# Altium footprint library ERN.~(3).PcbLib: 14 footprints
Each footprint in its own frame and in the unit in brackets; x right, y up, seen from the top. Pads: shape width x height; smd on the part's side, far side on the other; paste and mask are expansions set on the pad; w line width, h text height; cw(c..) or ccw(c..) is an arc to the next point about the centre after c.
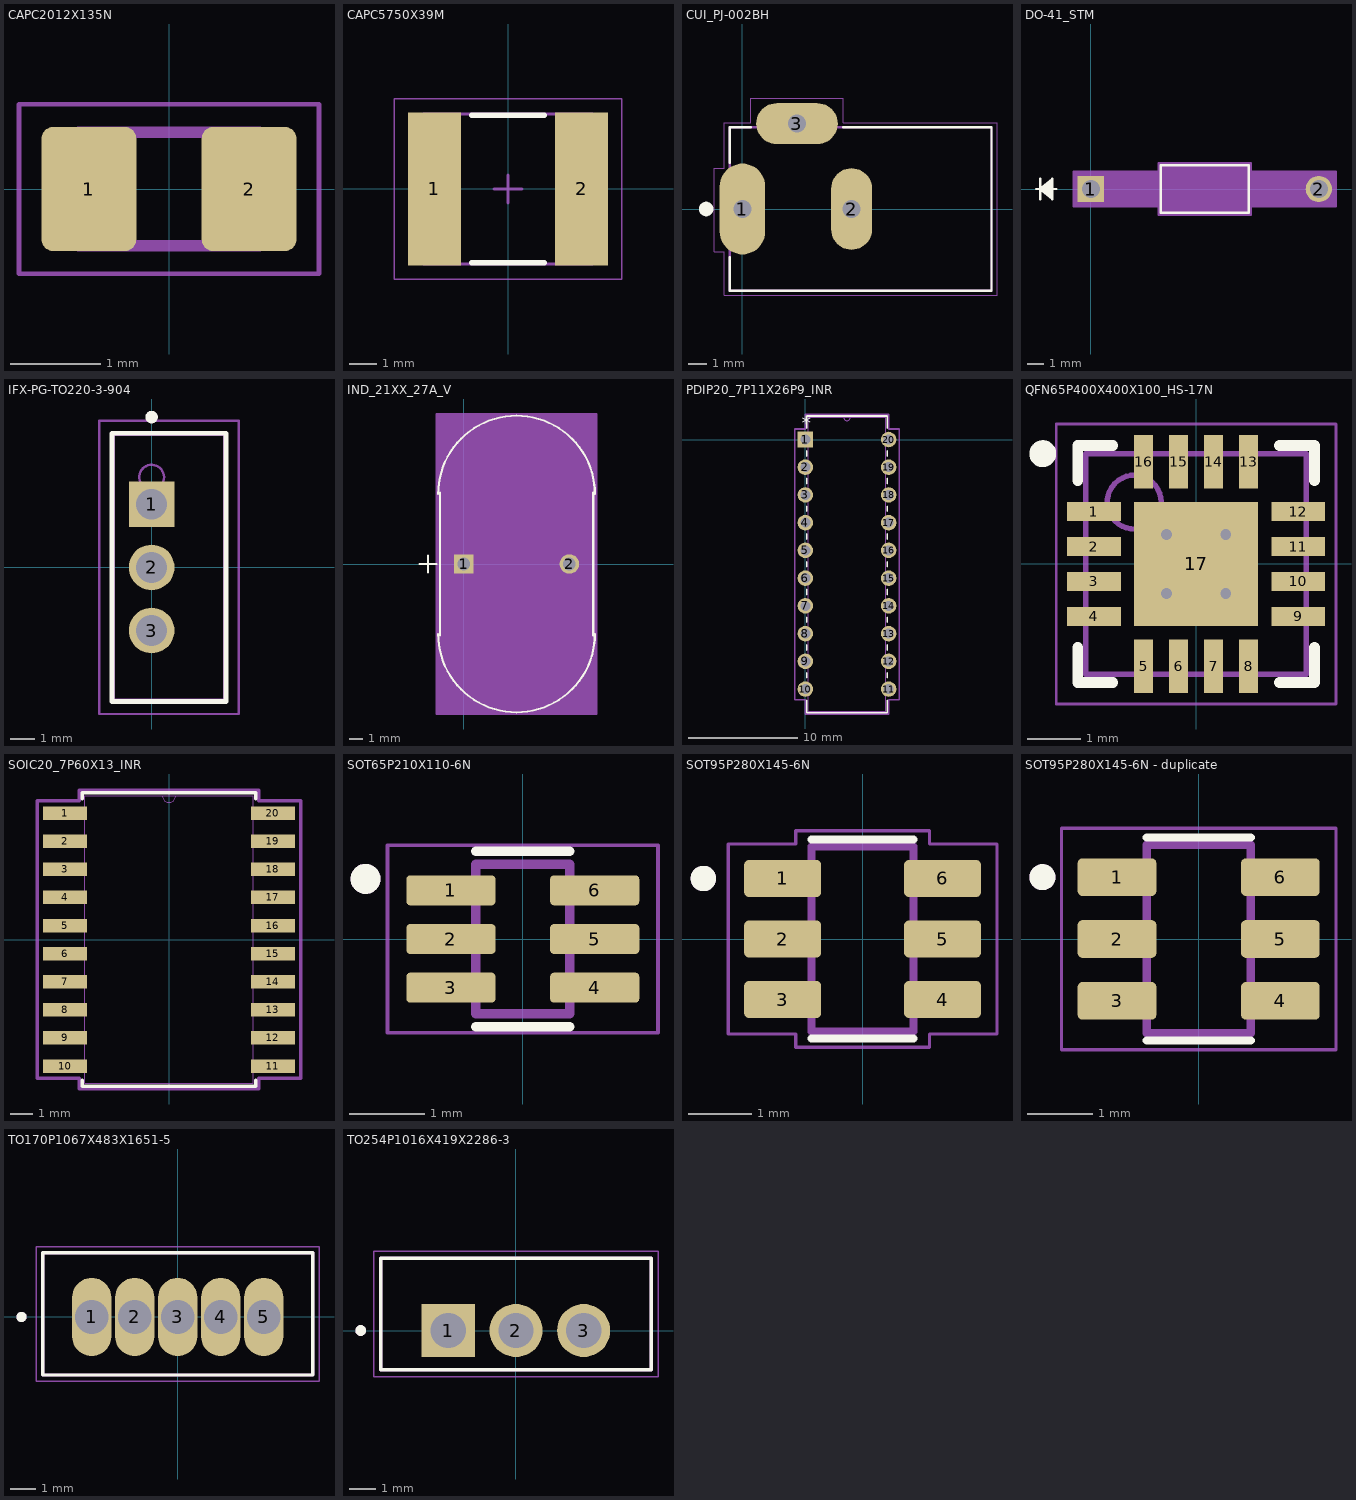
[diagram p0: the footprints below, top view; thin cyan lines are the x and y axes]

## CAPC2012X135N [mm]
pads (2):
  rrect25% 1.05x1.38 smd paste+0 mask+0.102: 1(-0.888,0) 2(0.888,0)
Mechanical 13:
  lines w0.127: -1,-0.63 1,-0.63 1,0.63 -1,0.63 -1,-0.63
Mechanical 15:
  lines w0.05: -1.663,-0.94 1.663,-0.94 1.663,0.94 -1.663,0.94 -1.663,-0.94
3D body "step_temp.STEP": height 1.35, standoff 0, extent -1,-0.625 1,0.625

## CAPC5750X39M [mm] "Chip Capacitor, 2-Leads, Body 5.70x5.00mm, IPC Low Density"
height 3.9
pads (2):
  rect 1.9x5.5 smd: 1(-2.65,0) 2(2.65,0)
Top Overlay:
  lines w0.2: -1.3,-2.65 1.3,-2.65 ; -1.3,2.65 1.3,2.65
Mechanical 13:
  lines w0.1: -3.05,-2.7 -3.05,2.7 3.05,2.7 3.05,-2.7 -3.05,-2.7
Mechanical 15:
  lines w0.05: -4.1,-3.25 -4.1,3.25 4.1,3.25 4.1,-3.25 -4.1,-3.25
  lines w0.1: -0.5,0 0.5,0 ; 0,-0.5 0,0.5
3D body "CAPC5750X39M.step": height 3.9, standoff 0, extent -3.05,-2.7 3.05,2.7

## CUI_PJ-002BH [mm]
pads (3):
  oval 2.5x5 hole 1 square: 1(0,0)
  oval 2.25x4.5 hole 1 square: 2(6,0)
  oval 4.5x2.25 hole 1 square: 3(3,4.7)
Top Overlay:
  circle w0.4: c-2,0 r0.2
  lines w0.127: -0.7,-2.65 -0.7,-4.5 13.7,-4.5 13.7,4.5 5.55,4.5 ; -0.7,2.55 -0.7,4.5 0.45,4.5
Mechanical 13:
  lines w0.127: -0.7,-4.5 13.7,-4.5 13.7,4.5 -0.7,4.5 -0.7,-4.5
Mechanical 15:
  lines w0.05: -1.55,-2.35 -1.55,2.25 -1,2.25 -1,4.75 0.45,4.75 0.45,6.1 5.55,6.1 5.55,4.75 14,4.75 14,-4.75 -1,-4.75 -1,-2.35 -1.55,-2.35
3D body "step_temp.STEP": height 4.5, standoff -10, extent -0.723,-4.701 13.677,4.699

## DO-41_STM [mil]
pads (2):
  rect 64x64 hole 44 paste-99999 mask+0: 1(0,0)
  round 64 hole 44 paste-99999 mask+0: 2(557,0)
Top Overlay:
  lines w6: -134,0 -84,0 ; -124,-25 -124,25 ; -94,-20 -124,0 ; -94,-15 -124,0 ; -94,-10 -124,0 ; -94,-5 -124,0 ; -94,5 -124,0 ; -94,10 -124,0 ; -94,15 -124,0 ; -94,20 -124,0 ; -124,0 -94,-25 -94,25 -124,0 ; 171,-58 171,58 386,58 386,-58 171,-58
  text ".Designator" at 141,-25 h50
Mechanical 13:
  lines w1: -134,0 -84,0 ; -124,-25 -124,25 ; -94,-20 -124,0 ; -94,-15 -124,0 ; -94,-10 -124,0 ; -94,-5 -124,0 ; -94,5 -124,0 ; -94,10 -124,0 ; -94,15 -124,0 ; -94,20 -124,0 ; 0,0 176,0 ; 381,0 557,0 ; -124,0 -94,-25 -94,25 -124,0 ; 176,-53 176,53 381,53 381,-53 176,-53
  text ".Designator" at 141,-25 h50
Mechanical 15:
  region: 381,-53 176,-53 176,53 381,53
  region: 166,-42 -42,-42 -42,42 166,42 166,63 391,63 391,42 599,42 599,-42 391,-42 391,-63 166,-63
  lines w6: -42,-42 166,-42 166,-63 391,-63 391,-42 599,-42 599,42 391,42 391,63 166,63 166,42 -42,42 -42,-42
3D body "DO-41_STM.step": height 106.06, standoff -100, extent -17.01,-52.71 574.02,52.71

## IFX-PG-TO220-3-904 [mm] "TO,flange mount,2.54mm pitch;3 pin,4.45mm L X 10.66mm W X 19.15mm H body"
height 19.15
pads (3):
  rect 1.84x1.84 hole 1.24 paste-2539.97 mask+0: 1(0,2.54)
  round 1.84 hole 1.24 paste-2539.97 mask+0: 2(0,0) 3(0,-2.54)
Top Overlay:
  circle w0.25: c0,6.05 r0.125
  lines w0.2: -1.6,-5.4 -1.6,5.4 3,5.4 3,-5.4 -1.6,-5.4
Mechanical 3:
  text ".DESIGNATOR" at 0,0 h1.2
Mechanical 13:
  circle w0.1: c0,3.632 r0.5
  lines w0.1: -1.52,-5.33 -1.52,5.33 2.93,5.33 2.93,-5.33 -1.52,-5.33
Mechanical 15:
  lines w0.1: -0.5,0 0.5,0 ; 0,-0.5 0,0.5 ; -2.1,-5.9 -2.1,5.9 3.5,5.9 3.5,-5.9 -2.1,-5.9
3D body "PG-TO220-3-904_Z8B00185321_V03_3D.stp": height 19.1, standoff -9.85, extent -1.53,-5.33 2.93,5.33

## IND_21XX_27A_V [mil]
pads (2):
  rect 57x57 hole 37 paste-99999 mask+0: 1(0,0)
  round 57 hole 37 paste-99999 mask+0: 2(310,0)
Top Overlay:
  lines w6: -130,0 -80,0 ; -105,-25 -105,25 ; -75,-205 ccw(c155,-205) 385,-205 ; -75,205 cw(c155,205) 385,205 ; -70,-210 -70,210 ; 380,-210 380,210
  text ".Designator" at 17.5,-25 h50
Mechanical 13:
  lines w1: -130,0 -80,0 ; -105,-25 -105,25 ; -70,-205 ccw(c155,-205) 380,-205 380,205 ccw(c155,205) -70,205 -70,-205
  text ".Designator" at 17.5,-25 h50
Mechanical 15:
  region: 390,-440 -80,-440 -80,440 390,440
  lines w6: -80,-440 -80,440 390,440 390,-440 -80,-440

## PDIP20_7P11X26P9_INR [mil]
pads (20):
  rect 56x56 hole 36 paste-99999 mask+0: 1(0,0)
  round 56 hole 36 paste-99999 mask+0: 2(0,-100) 3(0,-200) 4(0,-300) 5(0,-400) 6(0,-500) 7(0,-600) 8(0,-700) 9(0,-800) 10(0,-900) 11(300,-900) 12(300,-800) 13(300,-700) 14(300,-600) 15(300,-500) 16(300,-400) 17(300,-300) 18(300,-200) 19(300,-100) 20(300,0)
Top Overlay:
  lines w6: 5,-940.79 5,-985 295,-985 295,-940.79 ; 5,-859.21 5,-840.79 ; 5,-759.21 5,-740.79 ; 5,-659.21 5,-640.79 ; 5,-559.21 5,-540.79 ; 5,-459.21 5,-440.79 ; 5,-359.21 5,-340.79 ; 5,-259.21 5,-240.79 ; 5,-159.21 5,-140.79 ; 5,-59.21 5,-41.1 ; 5,41.1 5,85 295,85 295,40.79 ; 295,-859.21 295,-840.79 ; 295,-759.21 295,-740.79 ; 295,-659.21 295,-640.79 ; 295,-559.21 295,-540.79 ; 295,-459.21 295,-440.79 ; 295,-359.21 295,-340.79 ; 295,-259.21 295,-240.79 ; 295,-159.21 295,-140.79 ; 295,-59.21 295,-40.79
  text "*" at -12.5,33 h50
  text ".Designator" at 12.5,-475 h50
Mechanical 13:
  lines w1: 138,80 ccw(c150,80) 162,80 ; -18,-918 -18,-882 10,-882 10,-918 -18,-918 ; -18,-818 -18,-782 10,-782 10,-818 -18,-818 ; -18,-718 -18,-682 10,-682 10,-718 -18,-718 ; -18,-618 -18,-582 10,-582 10,-618 -18,-618 ; -18,-518 -18,-482 10,-482 10,-518 -18,-518 ; -18,-418 -18,-382 10,-382 10,-418 -18,-418 ; -18,-318 -18,-282 10,-282 10,-318 -18,-318 ; -18,-218 -18,-182 10,-182 10,-218 -18,-218 ; -18,-118 -18,-82 10,-82 10,-118 -18,-118 ; -18,-18 -18,18 10,18 10,-18 -18,-18 ; 10,-980 290,-980 290,80 10,80 10,-980 ; 290,-918 290,-882 318,-882 318,-918 290,-918 ; 290,-818 290,-782 318,-782 318,-818 290,-818 ; 290,-718 290,-682 318,-682 318,-718 290,-718 ; 290,-618 290,-582 318,-582 318,-618 290,-618 ; 290,-518 290,-482 318,-482 318,-518 290,-518 ; 290,-418 290,-382 318,-382 318,-418 290,-418 ; 290,-318 290,-282 318,-282 318,-318 290,-318 ; 290,-218 290,-182 318,-182 318,-218 290,-218 ; 290,-118 290,-82 318,-82 318,-118 290,-118 ; 290,-18 290,18 318,18 318,-18 290,-18
  text ".Designator" at 12.5,-475 h50
  text "*" at 7.5,-25 h50
Mechanical 15:
  lines w6: -38,-938 -38,38 0,38 0,90 300,90 300,38 338,38 338,-938 300,-938 300,-990 0,-990 0,-938 -38,-938
3D body "PDIP20_7P11X26P9_INR.step": height 217.09, standoff -100, extent -7.01,-980 320.98,80

## QFN65P400X400X100_HS-17N [mm] "QFN, 16-Leads, Body 4.00x4.00mm, Pitch 0.65mm, Thermal Pad 2.30x2.30mm, IPC Medium Density"
height 1
pads (17):
  rect 1x0.35 smd: 1(-1.9,0.975) 2(-1.9,0.325) 3(-1.9,-0.325) 4(-1.9,-0.975) 9(1.9,-0.975) 10(1.9,-0.325) 11(1.9,0.325) 12(1.9,0.975)
  rect 0.35x1 smd: 5(-0.975,-1.9) 6(-0.325,-1.9) 7(0.325,-1.9) 8(0.975,-1.9) 13(0.975,1.9) 14(0.325,1.9) 15(-0.325,1.9) 16(-0.975,1.9)
  rect 2.3x2.3 smd: 17(0,0)
via -0.55,0.55 diameter 0.5 hole 0.2
via 0.55,0.55 diameter 0.5 hole 0.2
via -0.55,-0.55 diameter 0.5 hole 0.2
via 0.55,-0.55 diameter 0.5 hole 0.2
Top Overlay:
  circle w0.25: c-2.85,2.05 r0.125
  lines w0.2: -2.2,-1.55 -2.2,-2.2 -1.55,-2.2 ; -2.2,1.55 -2.2,2.2 -1.55,2.2 ; 1.55,-2.2 2.2,-2.2 2.2,-1.55 ; 1.55,2.2 2.2,2.2 2.2,1.55
Mechanical 13:
  circle w0.1: c-1.15,1.15 r0.5
  lines w0.1: -2.05,-2.05 -2.05,2.05 2.05,2.05 2.05,-2.05 -2.05,-2.05
Mechanical 15:
  lines w0.05: -2.6,-2.6 -2.6,2.6 2.6,2.6 2.6,-2.6 -2.6,-2.6
  lines w0.1: -0.5,0 0.5,0 ; 0,-0.5 0,0.5
3D body "QFN65P400X400X100_HS-17N.step": height 1, standoff 0, extent -2.051,-2.051 2.051,2.051

## SOIC20_7P60X13_INR [mil]
pads (20):
  rect 79x24 smd paste+0 mask+0: 1(-185.04,225) 2(-185.04,175) 3(-185.04,125) 4(-185.04,75) 5(-185.04,25) 6(-185.04,-25) 7(-185.04,-75) 8(-185.04,-125) 9(-185.04,-175) 10(-185.04,-225) 11(185.04,-225) 12(185.04,-175) 13(185.04,-125) 14(185.04,-75) 15(185.04,-25) 16(185.04,25) 17(185.04,75) 18(185.04,125) 19(185.04,175) 20(185.04,225)
Top Overlay:
  lines w6: -154.61,-250.1 -154.61,-260.91 154.61,-260.91 154.61,-250.1 ; -154.61,250.1 -154.61,260.91 154.61,260.91 154.61,250.1
  text ".Designator" at -245,300 h50
Mechanical 13:
  lines w1: -12,255.91 ccw(c0,255.91) 12,255.91 ; -149.61,-255.91 -149.61,255.91 149.61,255.91 149.61,-255.91 -149.61,-255.91
Mechanical 15:
  lines w6: -234.54,-247 -159.61,-247 -159.61,-265.91 159.61,-265.91 159.61,-247 234.54,-247 234.54,247 159.61,247 159.61,265.91 -159.61,265.91 -159.61,247 -234.54,247 -234.54,-247
3D body "SOIC20_7P60X13_INR.step": height 104.33, standoff 0, extent -210.75,-255.91 210.75,255.91

## SOT65P210X110-6N [mm]
pads (6):
  rrect25% 1.19x0.4 smd: 1(-0.96,0.65) 2(-0.96,0) 3(-0.96,-0.65) 4(0.96,-0.65) 5(0.96,0) 6(0.96,0.65)
Top Overlay:
  circle w0.2: c-2.1,0.802 r0.1
  lines w0.127: -0.625,-1.17 0.625,-1.17 ; -0.625,1.17 0.625,1.17
Mechanical 13:
  circle w0.2: c-2.1,0.802 r0.1
  lines w0.127: -0.625,-1 -0.625,1 0.625,1 0.625,-1 -0.625,-1
Mechanical 15:
  lines w0.05: -1.805,-1.25 -1.805,1.25 1.805,1.25 1.805,-1.25 -1.805,-1.25
3D body "step_temp.STEP": height 1.1, standoff 0, extent -1.05,-1 1.05,1

## SOT95P280X145-6N [mm]
height 1.45
pads (6):
  rrect25% 1.21x0.58 smd: 1(-1.255,0.95) 2(-1.255,0) 3(-1.255,-0.95) 4(1.255,-0.95) 5(1.255,0) 6(1.255,0.95)
Top Overlay:
  circle w0.2: c-2.5,0.95 r0.1
  lines w0.127: -0.8,-1.56 0.8,-1.56 ; -0.8,1.56 0.8,1.56
Mechanical 13:
  circle w0.2: c-2.5,0.95 r0.1
  lines w0.127: -0.8,-1.45 0.8,-1.45 0.8,1.45 -0.8,1.45 -0.8,-1.45
Mechanical 15:
  lines w0.05: -2.11,-1.49 -1.05,-1.49 -1.05,-1.7 1.05,-1.7 1.05,-1.49 2.11,-1.49 2.11,1.49 1.05,1.49 1.05,1.7 -1.05,1.7 -1.05,1.49 -2.11,1.49 -2.11,-1.49
3D body "step_temp.STEP": height 1.45, standoff 0, extent -1.4,-1.45 1.4,1.45

## SOT95P280X145-6N - duplicate [mm]
height 1.45
pads (6):
  rrect25% 1.21x0.58 smd: 1(-1.255,0.95) 2(-1.255,0) 3(-1.255,-0.95) 4(1.255,-0.95) 5(1.255,0) 6(1.255,0.95)
Top Overlay:
  circle w0.2: c-2.4,0.95 r0.1
  lines w0.127: -0.8,-1.56 0.8,-1.56 ; -0.8,1.56 0.8,1.56
Mechanical 13:
  circle w0.2: c-2.4,0.95 r0.1
  lines w0.127: -0.8,-1.45 -0.8,1.45 0.8,1.45 0.8,-1.45 -0.8,-1.45
Mechanical 15:
  lines w0.05: -2.11,-1.7 -2.11,1.7 2.11,1.7 2.11,-1.7 -2.11,-1.7
3D body "step_temp.STEP": height 1.45, standoff 0, extent -1.4,-1.45 1.4,1.45

## TO170P1067X483X1651-5 [mm]
height 16.51
pads (5):
  oval 1.55x3.1 hole 1.34: 1(-3.4,0) 2(-1.7,0) 3(0,0) 4(1.7,0) 5(3.4,0)
Top Overlay:
  circle w0.2: c-6.175,0 r0.1
  lines w0.127: -5.335,-2.29 -5.335,2.54 5.335,2.54 5.335,-2.29 -5.335,-2.29
Mechanical 13:
  circle w0.2: c-6.175,0 r0.1
  lines w0.127: -5.335,-2.29 -5.335,2.54 5.335,2.54 5.335,-2.29 -5.335,-2.29
Mechanical 15:
  lines w0.05: -5.585,-2.54 -5.585,2.775 5.585,2.775 5.585,-2.54 -5.585,-2.54
3D body "step_temp.STEP": height 16.84, standoff -14.73, extent -5.08,0 5.08,4.445

## TO254P1016X419X2286-3 [mm]
height 22.86
pads (3):
  rect 1.995x1.995 / inner round 1.995 / far side rect 1.995x1.995 hole 1.33: 1(-2.54,0)
  round 1.995 hole 1.33: 2(0,0) 3(2.54,0)
Top Overlay:
  circle w0.2: c-5.83,0 r0.1
  lines w0.127: -5.08,-1.478 5.08,-1.478 5.08,2.718 -5.08,2.718 -5.08,-1.478
Mechanical 13:
  circle w0.2: c-5.83,0 r0.1
  lines w0.127: -5.08,-1.478 5.08,-1.478 5.08,2.718 -5.08,2.718 -5.08,-1.478
Mechanical 15:
  lines w0.05: -5.33,-1.727 -5.33,2.967 5.33,2.967 5.33,-1.727 -5.33,-1.727
3D body "step_temp.STEP": height 22.86, standoff -8.38, extent -5.08,-1.473 5.08,2.718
